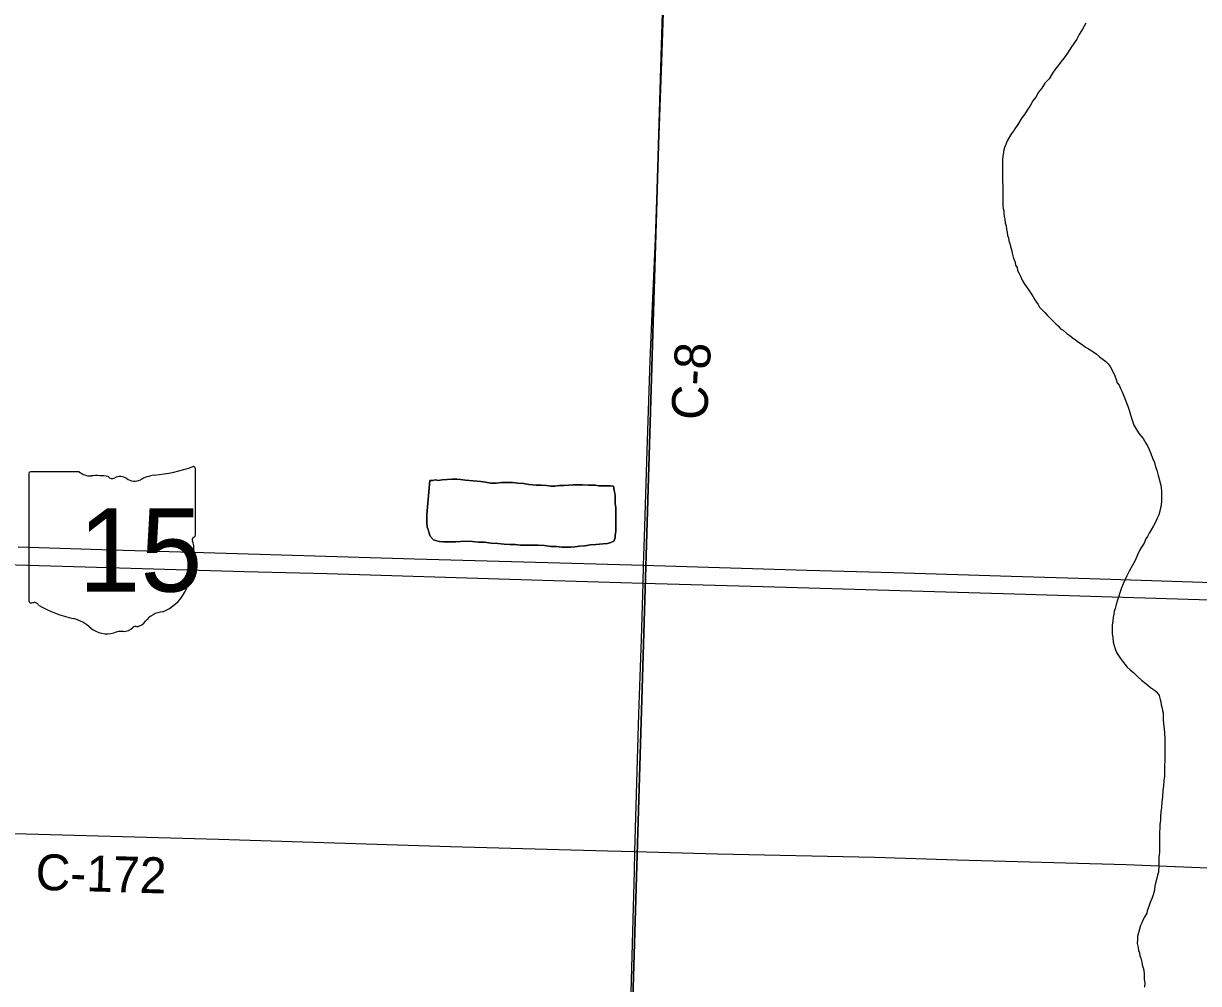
# Model space of a CAD drawing. Extents: x 1587405 to 1714697, y 1028970 to 1155083.
# Drawn here: x 1663879 to 1668786, y 1087792 to 1091803 of the extents above; entities that cross this region are included whole.
import ezdxf

# ---------------------------------------------------------------- set-up
doc = ezdxf.new("R2010")
doc.units = 0
for name, color, linetype in [('GM_X_County_Road', 7, 'Continuous'), ('GM_X_County_Road_Text', 7, 'Continuous'), ('GM_X_Minor_Lake', 7, 'Continuous'), ('GM_X_Minor_River', 7, 'Continuous'), ('GM_X_Section', 7, 'Continuous'), ('GM_X_State_Route', 7, 'Continuous'), ('GM_X_State_Shield', 7, 'Continuous')]:
    doc.layers.add(name, color=color, linetype=linetype)

msp = doc.modelspace()

# ---------------------------------------------------------------- linework, layer by layer
at = {"layer": 'GM_X_County_Road'}
for points in [[(1666468.4, 1089539.4), (1666471.6, 1089656.7), (1666483.5, 1090017.4), (1666496.4, 1090394.5), (1666505.4, 1090623.4), (1666518.6, 1090902.9), (1666527.2, 1091148.7), (1666544.5, 1091642.9), (1666553.6, 1091886.4), (1666558.8, 1091977), (1666562.3, 1092020.2), (1666565.8, 1092049.3), (1666571.8, 1092078), (1666578.8, 1092093.1), (1666589.2, 1092113.1), (1666599.1, 1092127.3), (1666614.5, 1092145.3)], [(1666466.3, 1089465.4), (1666468.4, 1089539.4)], [(1666432.5, 1088343.7), (1666448.8, 1088918.8), (1666459.8, 1089230.3), (1666466.3, 1089465.4)], [(1661065.2, 1088489.7), (1661084.9, 1088489), (1661421.7, 1088477.6), (1661789.6, 1088470.6), (1662938, 1088439.8), (1663840.5, 1088418.7), (1664693.6, 1088394.8), (1665661.5, 1088364.7), (1666317.7, 1088346.7), (1666432.5, 1088343.7)], [(1666333.8, 1084353.1), (1666336.7, 1084490.2), (1666344.5, 1084900.3), (1666361.5, 1085589.2), (1666371.8, 1085966.4), (1666379.5, 1086310.9), (1666390.7, 1086852.3), (1666399.4, 1087163.9), (1666410, 1087541.1), (1666416.8, 1087754.2), (1666430.1, 1088262.7), (1666432.5, 1088343.7)], [(1666432.5, 1088343.7), (1666777.1, 1088334.7), (1667433.2, 1088320.4), (1667777.7, 1088309), (1668483.1, 1088289.9), (1668860.3, 1088274.7), (1669008, 1088272.9), (1669286.8, 1088283.3), (1669450.9, 1088281.4), (1670615.7, 1088248.2), (1671124.2, 1088233.9), (1671316.8, 1088224.3), (1671504.8, 1088214.3), (1671816.4, 1088190.1)]]:
    msp.add_lwpolyline(points, dxfattribs=at)
at = {"layer": 'GM_X_Minor_Lake'}
for points in [[(1665575.7, 1089893.9), (1665579.7, 1089893.9), (1665587.7, 1089893.9), (1665597.8, 1089895.9), (1665611.8, 1089893.8), (1665627.9, 1089895.8), (1665648, 1089897.7), (1665668, 1089899.6), (1665688.1, 1089899.6), (1665704.2, 1089897.5), (1665724.2, 1089895.5), (1665788.4, 1089889.2), (1665808.5, 1089887.2), (1665830.5, 1089883.1), (1665852.6, 1089883), (1665874.7, 1089884.9), (1665898.8, 1089884.9), (1665920.9, 1089884.8), (1665942.9, 1089882.7), (1665967, 1089880.6), (1665989.1, 1089876.6), (1666019.2, 1089874.4), (1666041.2, 1089874.4), (1666063.3, 1089872.3), (1666081.4, 1089870.2), (1666097.4, 1089870.2), (1666117.5, 1089872.1), (1666135.6, 1089872.1), (1666155.6, 1089874), (1666173.7, 1089876), (1666191.8, 1089875.9), (1666213.8, 1089875.8), (1666237.9, 1089873.7), (1666254, 1089873.7), (1666268, 1089873.6), (1666280.1, 1089871.6), (1666292.1, 1089871.6), (1666306.1, 1089871.5), (1666320.2, 1089871.5), (1666330.2, 1089871.4), (1666342.3, 1089869.4), (1666346.2, 1089851.3), (1666348.2, 1089841.3), (1666350.2, 1089829.2), (1666350.2, 1089813.2), (1666350.1, 1089797.1), (1666352.1, 1089779.1), (1666352.1, 1089767), (1666352, 1089753), (1666352, 1089740.9), (1666352, 1089726.9), (1666351.9, 1089714.9), (1666351.9, 1089680.8), (1666349.8, 1089664.7), (1666349.8, 1089654.7), (1666343.7, 1089640.6), (1666331.7, 1089634.7), (1666317.6, 1089630.7), (1666299.6, 1089628.7), (1666269.5, 1089626.8), (1666247.4, 1089624.9), (1666223.3, 1089621), (1666201.2, 1089619), (1666181.1, 1089617.1), (1666165.1, 1089615.1), (1666147, 1089615.2), (1666126.9, 1089615.2), (1666104.9, 1089617.3), (1666080.8, 1089617.4), (1666054.7, 1089621.5), (1666028.6, 1089623.6), (1665996.5, 1089623.7), (1665974.4, 1089623.8), (1665954.4, 1089623.8), (1665932.3, 1089625.9), (1665910.2, 1089626), (1665886.2, 1089628.1), (1665860.1, 1089630.1), (1665832, 1089632.2), (1665803.9, 1089636.3), (1665777.8, 1089636.4), (1665753.7, 1089638.5), (1665725.6, 1089640.6), (1665703.6, 1089638.7), (1665683.5, 1089636.7), (1665669.4, 1089636.8), (1665655.4, 1089636.8), (1665643.3, 1089636.9), (1665633.3, 1089636.9), (1665615.3, 1089639), (1665591.2, 1089645.1), (1665577.2, 1089661.2), (1665571.2, 1089677.2), (1665569.2, 1089689.3), (1665565.2, 1089699.3), (1665563.3, 1089719.4), (1665563.3, 1089751.5), (1665575.7, 1089893.9)], [(1665575.7, 1089893.9), (1665563.3, 1089751.5), (1665563.3, 1089719.4), (1665565.2, 1089699.3), (1665569.2, 1089689.3), (1665571.2, 1089677.2), (1665577.2, 1089661.2), (1665591.2, 1089645.1), (1665615.3, 1089639), (1665633.3, 1089636.9), (1665643.3, 1089636.9), (1665655.4, 1089636.8), (1665669.4, 1089636.8), (1665683.5, 1089636.7), (1665703.6, 1089638.7), (1665725.6, 1089640.6), (1665753.7, 1089638.5), (1665777.8, 1089636.4), (1665803.9, 1089636.3), (1665832, 1089632.2), (1665860.1, 1089630.1), (1665886.2, 1089628.1), (1665910.2, 1089626), (1665932.3, 1089625.9), (1665954.4, 1089623.8), (1665974.4, 1089623.8), (1665996.5, 1089623.7), (1666028.6, 1089623.6), (1666054.7, 1089621.5), (1666080.8, 1089617.4), (1666104.9, 1089617.3), (1666126.9, 1089615.2), (1666147, 1089615.2), (1666165.1, 1089615.1), (1666181.1, 1089617.1), (1666201.2, 1089619), (1666223.3, 1089621), (1666247.4, 1089624.9), (1666269.5, 1089626.8), (1666299.6, 1089628.7), (1666317.6, 1089630.7), (1666331.7, 1089634.7), (1666343.7, 1089640.6), (1666349.8, 1089654.7), (1666349.8, 1089664.7), (1666351.9, 1089680.8), (1666351.9, 1089714.9), (1666352, 1089726.9), (1666352, 1089740.9), (1666352, 1089753)], [(1666352, 1089753), (1666352.1, 1089767), (1666352.1, 1089779.1), (1666350.1, 1089797.1), (1666350.2, 1089813.2), (1666350.2, 1089829.2), (1666348.2, 1089841.3), (1666346.2, 1089851.3), (1666342.3, 1089869.4), (1666330.2, 1089871.4), (1666320.2, 1089871.5), (1666306.1, 1089871.5), (1666292.1, 1089871.6), (1666280.1, 1089871.6), (1666268, 1089873.6), (1666254, 1089873.7), (1666237.9, 1089873.7), (1666213.8, 1089875.8), (1666191.8, 1089875.9), (1666173.7, 1089876), (1666155.6, 1089874), (1666135.6, 1089872.1), (1666117.5, 1089872.1), (1666097.4, 1089870.2), (1666081.4, 1089870.2), (1666063.3, 1089872.3), (1666041.2, 1089874.4), (1666019.2, 1089874.4), (1665989.1, 1089876.6), (1665967, 1089880.6), (1665942.9, 1089882.7), (1665920.9, 1089884.8), (1665898.8, 1089884.9), (1665874.7, 1089884.9), (1665852.6, 1089883), (1665830.5, 1089883.1), (1665808.5, 1089887.2), (1665788.4, 1089889.2), (1665724.2, 1089895.5), (1665704.2, 1089897.5), (1665688.1, 1089899.6), (1665668, 1089899.6), (1665648, 1089897.7), (1665627.9, 1089895.8), (1665611.8, 1089893.8), (1665597.8, 1089895.9), (1665587.7, 1089893.9), (1665579.7, 1089893.9), (1665575.7, 1089893.9)]]:
    msp.add_lwpolyline(points, dxfattribs=at)
at = {"layer": 'GM_X_Minor_River'}
for points in [[(1668315.4, 1091803.5), (1668301.3, 1091779.4), (1668287.2, 1091757.4), (1668277.1, 1091737.4), (1668265, 1091719.4), (1668253, 1091701.3), (1668238.9, 1091679.3), (1668224.8, 1091659.3), (1668212.7, 1091643.3)], [(1668212.7, 1091643.3), (1668200.6, 1091629.3), (1668188.5, 1091613.2), (1668176.5, 1091595.2), (1668162.4, 1091571.2), (1668144.3, 1091553.2), (1668132.2, 1091533.2), (1668118.1, 1091515.2), (1668106, 1091495.1), (1668093.9, 1091479.1), (1668083.8, 1091461.1), (1668069.7, 1091441.1), (1668059.7, 1091423), (1668047.6, 1091409), (1668039.5, 1091395), (1668031.5, 1091381), (1668019.4, 1091363), (1668013.3, 1091353), (1668005.3, 1091342.9), (1667987.2, 1091312.9), (1667981.1, 1091296.9), (1667975.1, 1091284.8), (1667973, 1091274.8), (1667971, 1091264.8), (1667968.9, 1091246.7), (1667966.9, 1091234.7), (1667966.9, 1091224.7), (1667966.9, 1091212.6), (1667966.8, 1091200.6), (1667966.8, 1091188.6), (1667966.8, 1091172.5), (1667966.7, 1091158.5), (1667966.7, 1091142.4), (1667968.7, 1091124.3), (1667968.6, 1091110.3), (1667968.6, 1091092.2), (1667968.6, 1091072.2), (1667968.5, 1091054.1), (1667968.5, 1091040.1), (1667970.5, 1091030), (1667972.4, 1091020), (1667972.4, 1091010), (1667974.4, 1090995.9), (1667976.4, 1090985.9), (1667978.3, 1090969.8), (1667982.3, 1090957.8), (1667984.3, 1090943.7), (1667986.3, 1090929.6), (1667988.3, 1090917.6), (1667992.3, 1090907.6), (1667994.2, 1090895.5), (1667998.2, 1090883.5), (1668000.2, 1090871.4), (1668006.2, 1090853.3), (1668008.2, 1090843.3), (1668012.1, 1090827.2), (1668016.1, 1090815.2), (1668020.1, 1090805.1), (1668022.1, 1090793.1), (1668028.1, 1090783), (1668030.1, 1090771), (1668036.1, 1090760.9), (1668042.1, 1090746.9), (1668050, 1090730.8), (1668058, 1090716.7), (1668080, 1090684.6), (1668088, 1090672.5), (1668096, 1090660.4), (1668102, 1090648.3), (1668110, 1090638.3), (1668116, 1090628.2), (1668122, 1090618.2), (1668132, 1090608.1), (1668144.1, 1090596.1), (1668154.1, 1090584), (1668164.1, 1090573.9), (1668174.1, 1090563.8), (1668190.1, 1090547.7), (1668200.1, 1090539.7), (1668210.1, 1090527.6), (1668220.1, 1090521.6), (1668236.2, 1090507.5), (1668248.2, 1090499.4), (1668258.2, 1090491.3), (1668272.2, 1090481.3), (1668284.2, 1090471.2), (1668300.3, 1090461.1), (1668314.3, 1090451), (1668326.3, 1090443), (1668340.4, 1090434.9), (1668358.4, 1090422.8), (1668372.4, 1090410.7), (1668388.4, 1090398.6), (1668398.4, 1090390.6), (1668408.5, 1090380.5), (1668416.5, 1090370.4), (1668422.5, 1090360.4), (1668426.5, 1090350.3), (1668432.5, 1090340.3), (1668436.4, 1090330.2), (1668442.4, 1090316.2)], [(1668442.4, 1090316.2), (1668446.4, 1090302.1), (1668454.4, 1090292.1), (1668460.4, 1090278), (1668466.4, 1090263.9), (1668472.4, 1090249.9), (1668490.3, 1090203.6), (1668496.3, 1090187.6), (1668502.3, 1090167.5), (1668508.3, 1090145.4), (1668516.2, 1090125.3), (1668528.2, 1090103.2), (1668538.2, 1090089.1), (1668546.2, 1090079.1), (1668554.2, 1090069), (1668560.2, 1090058.9), (1668566.2, 1090048.9), (1668572.2, 1090038.8), (1668580.2, 1090022.8), (1668586.2, 1090006.7), (1668594.2, 1089986.6), (1668602.2, 1089968.5), (1668606.1, 1089950.4), (1668612.1, 1089936.4), (1668614.1, 1089926.3), (1668618.1, 1089914.3), (1668622.1, 1089900.2), (1668624.1, 1089888.2), (1668628.1, 1089874.1), (1668630, 1089862.1), (1668632, 1089850), (1668632, 1089838), (1668631.9, 1089821.9), (1668631.9, 1089809.9), (1668629.9, 1089789.8), (1668627.8, 1089779.8), (1668623.8, 1089765.8), (1668619.7, 1089749.7), (1668613.7, 1089735.7), (1668605.6, 1089719.7), (1668597.6, 1089703.7), (1668587.5, 1089687.6), (1668579.4, 1089673.6), (1668573.4, 1089659.6), (1668565.3, 1089649.6), (1668559.3, 1089631.6), (1668547.2, 1089615.5), (1668539.1, 1089601.5), (1668531.1, 1089583.5), (1668521, 1089559.4), (1668508.9, 1089537.4), (1668496.8, 1089515.4), (1668486.7, 1089495.3), (1668478.6, 1089477.3), (1668470.6, 1089461.3), (1668464.5, 1089445.2), (1668446.3, 1089389.1), (1668442.3, 1089375.1), (1668438.2, 1089359), (1668434.2, 1089347), (1668432.1, 1089335), (1668430.1, 1089322.9), (1668428.1, 1089306.9), (1668426, 1089288.8), (1668426, 1089272.8), (1668425.9, 1089254.7), (1668427.9, 1089236.7), (1668429.9, 1089218.6), (1668433.9, 1089204.5), (1668437.8, 1089190.5), (1668443.8, 1089174.4), (1668451.8, 1089162.3), (1668459.8, 1089150.3), (1668467.8, 1089138.2), (1668477.8, 1089126.1), (1668487.8, 1089114.1), (1668499.8, 1089102), (1668515.9, 1089089.9), (1668533.9, 1089071.8), (1668547.9, 1089059.7), (1668565.9, 1089045.6), (1668586, 1089029.5), (1668602, 1089017.4), (1668612, 1089009.3), (1668622, 1088995.2), (1668626, 1088979.2), (1668628, 1088969.1), (1668630, 1088957.1), (1668633.9, 1088943), (1668635.9, 1088933), (1668637.9, 1088923), (1668637.9, 1088908.9), (1668637.8, 1088894.9), (1668639.8, 1088876.8), (1668641.8, 1088856.7), (1668643.7, 1088838.7), (1668645.7, 1088814.6), (1668645.6, 1088798.5), (1668645.6, 1088778.5), (1668645.6, 1088760.4), (1668645.5, 1088738.3)], [(1668645.5, 1088738.3), (1668643.4, 1088688.2), (1668643.4, 1088674.1), (1668643.3, 1088658.1), (1668641.3, 1088640), (1668639.2, 1088617.9), (1668637.2, 1088597.9), (1668635.1, 1088573.8), (1668633, 1088549.8), (1668631, 1088527.7), (1668628.9, 1088509.6), (1668626.9, 1088491.6), (1668626.8, 1088473.5), (1668624.8, 1088457.5), (1668624.8, 1088439.4), (1668622.7, 1088425.4), (1668622.7, 1088407.3), (1668622.6, 1088381.2), (1668622.6, 1088359.2), (1668622.5, 1088339.1), (1668620.5, 1088321), (1668620.4, 1088305), (1668620.4, 1088288.9), (1668620.4, 1088276.9), (1668618.3, 1088266.9), (1668618.3, 1088256.8), (1668614.3, 1088244.8), (1668612.2, 1088232.8), (1668608.2, 1088216.7), (1668604.1, 1088198.7), (1668602.1, 1088186.6), (1668600.1, 1088176.6), (1668596, 1088162.6), (1668592, 1088150.6), (1668587.9, 1088140.6), (1668583.9, 1088130.5), (1668577.9, 1088114.5), (1668571.8, 1088096.4), (1668569.8, 1088086.4), (1668561.7, 1088072.4), (1668553.6, 1088056.4), (1668549.6, 1088046.4), (1668543.5, 1088034.3), (1668531.4, 1087988.2), (1668531.4, 1087974.2), (1668529.3, 1087960.1), (1668533.3, 1087942.1), (1668535.3, 1087930), (1668539.3, 1087920), (1668541.2, 1087907.9), (1668545.2, 1087897.9), (1668549.2, 1087881.8), (1668551.2, 1087869.8), (1668555.2, 1087857.7), (1668557.2, 1087847.7), (1668559.1, 1087829.6), (1668559.1, 1087819.6), (1668559.1, 1087809.6), (1668561.1, 1087795.5), (1668561, 1087777.4)]]:
    msp.add_lwpolyline(points, dxfattribs=at)
at = {"layer": 'GM_X_Section'}
for points in [[(1661264.4, 1092271), (1661358.4, 1092269.9), (1666555.8, 1092129.2), (1666401.8, 1086987.9), (1660988.4, 1087141.1)], [(1666555.8, 1092129.2), (1666653.8, 1092126.1), (1671935.5, 1091998.3), (1671767.3, 1086851.1), (1666401.8, 1086987.9)]]:
    msp.add_lwpolyline(points, close=True, dxfattribs=at)
at = {"layer": 'GM_X_State_Route'}
for points in [[(1663855.9, 1089615.9), (1664249.3, 1089603.6), (1664724.8, 1089589.9), (1665511.8, 1089567), (1666118.4, 1089549.3), (1666468.4, 1089539.4), (1666511.9, 1089538.3), (1667151.3, 1089519.2), (1667512.1, 1089509.5), (1668003.8, 1089494.3), (1668331.7, 1089484.1), (1669231.9, 1089455.1), (1669339.7, 1089453.4), (1669561.4, 1089449.1), (1669742.9, 1089441.8), (1670233.2, 1089427.2), (1670773.7, 1089411.3), (1671489.2, 1089390.8), (1671874.8, 1089379.5), (1672794.2, 1089353.7), (1673312.5, 1089338.9), (1673795.5, 1089323.8)], [(1663129.3, 1089562.6), (1664326.7, 1089527.5), (1664802.4, 1089513.6), (1665146.8, 1089504.9), (1665999.8, 1089479), (1666466.3, 1089465.4), (1666967.5, 1089450.6), (1668017.3, 1089419.6), (1668788.2, 1089396.4), (1669458.1, 1089378.1), (1669685.5, 1089369.9), (1670543.4, 1089347.3), (1670805.9, 1089341.7), (1671281.5, 1089326.4), (1671486.5, 1089320.5)]]:
    msp.add_lwpolyline(points, dxfattribs=at)
at = {"layer": 'GM_X_State_Shield'}
for p, q in [((1663900.7, 1089920.6), (1663900.7, 1089392.3)), ((1664111.4, 1089929.7), (1663907.5, 1089929.7)), ((1664596.8, 1089666.4), (1664596.8, 1089942.8)), ((1664596.7, 1089666.5), (1664596.8, 1089666.4))]:
    msp.add_line(p, q, dxfattribs=at)
for centre, radius, start, end in [((1664348.8, 1090650), 738.2, 275.8445, 288.9065), ((1664589, 1089943.9), 7.75, 351.8621, 97.738), ((1663908.7, 1089921.7), 8.06, 98.1301, 188.1301), ((1664159.9, 1089991), 78.2, 231.6195, 271.1119), ((1664185.9, 1089633.1), 280.8, 80.4867, 94.9883), ((1664249.6, 1089924.5), 22.6, 219.7921, 297.1024), ((1664282.7, 1089863.4), 46.9, 54.4667, 119.1411), ((1664343.3, 1089947.2), 56.4, 233.8562, 294.8282), ((1664443, 1089768.3), 148.5, 97.3462, 120.7689), ((1664595, 1089646.1), 12, 107.944, 210.337), ((1664588.5, 1089665.3), 8.29, 289.6038, 7.7341), ((1664518.7, 1089611.2), 72, 340.033, 23.6496), ((1664624.5, 1089550.8), 52.4, 136.8065, 186.9296), ((1664390.2, 1089515.6), 184.6, 292.3089, 8.9858), ((1663908.7, 1089391.1), 8.14, 171.9584, 258.3066), ((1663910, 1089445.2), 62.1, 267.339, 280.6039), ((1663922.7, 1089361.8), 22.4, 29.7484, 93.2717), ((1664205.3, 1089836.5), 533.1, 240.4129, 257.1985), ((1664046.4, 1089154.9), 166.8, 47.1842, 75.836), ((1664468, 1089244), 101.1, 94.4031, 142.5768), ((1664226.8, 1089359.2), 105.8, 230.7004, 286.2918), ((1664287.9, 1089176.5), 87, 85.6951, 111.2099), ((1664295.7, 1089319.6), 56.4, 268.777, 315.5493), ((1664346.7, 1089268.5), 15.9, 65.7517, 132.6484), ((1664339.9, 1089341.1), 59.7, 282.8732, 323.2771)]:
    msp.add_arc(centre, radius, start, end, dxfattribs=at)

# ---------------------------------------------------------------- texts
at = {"layer": 'GM_X_County_Road_Text'}
for s, rotation, p in [('C-8', 86.9706, (1666733.2, 1090143.4)), ('C-172', 358.3476, (1663927.7, 1088183.8))]:
    msp.add_text(s, height=150, rotation=rotation, dxfattribs=at).set_placement(p)
at = {"layer": 'GM_X_State_Shield'}
msp.add_text('15', height=348.05, dxfattribs=at).set_placement((1664107.9, 1089429.5))

doc.saveas('drawing.dxf')
